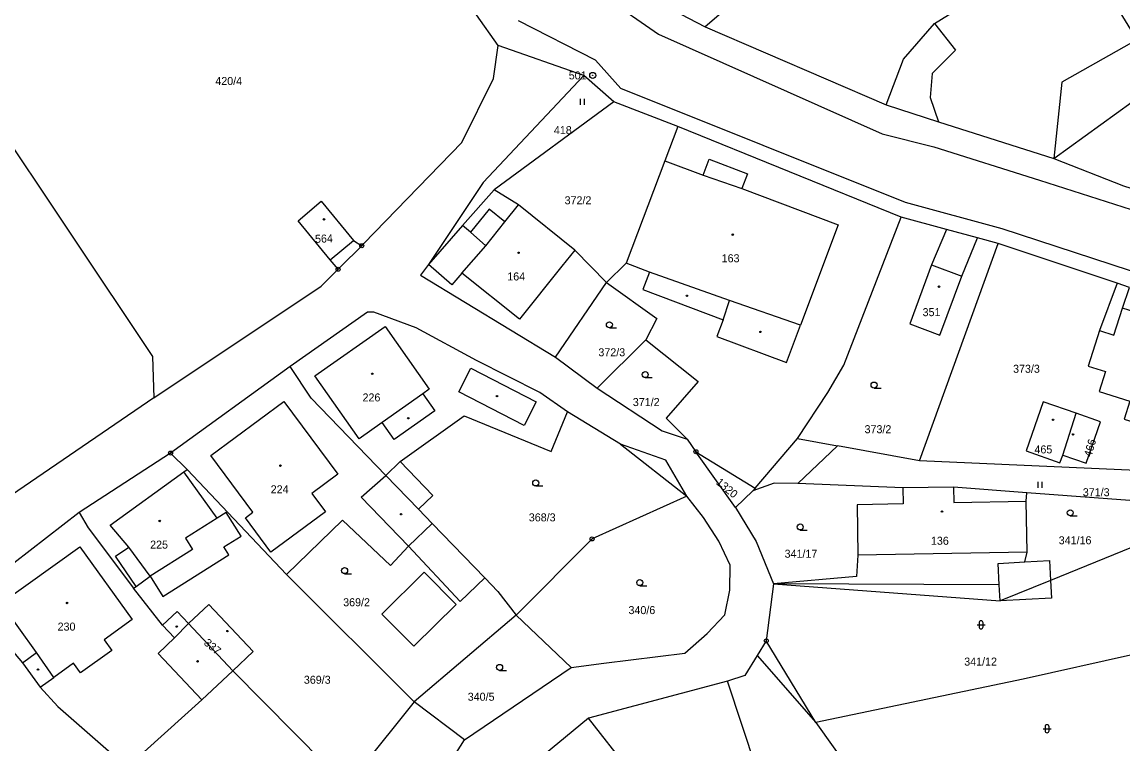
# Model space of a CAD drawing. Extents: x -745926 to -742978, y -968282 to -965689.
# Drawn here: x -744856.3 to -744718.8, y -966688.6 to -966598.4 of the extents above; entities that cross this region are included whole.
import ezdxf

# ---------------------------------------------------------------- set-up
doc = ezdxf.new("R2010")
doc.units = 0
for name, color, linetype in [('Hranice parcel', 7, 'Continuous'), ('Parcelní čísla', 7, 'Continuous'), ('Vnitřní kresba', 7, 'Continuous'), ('Značky bodu BP', 7, 'Continuous'), ('Značky budov', 7, 'Continuous'), ('Značky kultur', 7, 'Continuous')]:
    doc.layers.add(name, color=color, linetype=linetype)

msp = doc.modelspace()

# ---------------------------------------------------------------- linework, layer by layer
at = {"layer": 'Hranice parcel'}
for p, q in [((-744775.05, -966596.92), (-744770.98, -966599.02)), ((-744727.43, -966615.48), (-744701.27, -966596.5)), ((-744786.13, -966605.11), (-744796.84, -966601.38)), ((-744782.39, -966608.41), (-744786.13, -966605.11)), ((-744782.39, -966608.41), (-744797.33, -966619.38)), ((-744774.4, -966611.5), (-744782.39, -966608.41)), ((-744746.47, -966622.79), (-744774.4, -966611.5)), ((-744740.83, -966624.33), (-744746.47, -966622.79)), ((-744736.97, -966625.38), (-744740.83, -966624.33)), ((-744744.18, -966653.24), (-744734.36, -966626.09)), ((-744734.36, -966626.09), (-744736.97, -966625.38)), ((-744719.52, -966631.07), (-744734.36, -966626.09)), ((-744789.67, -966640.3), (-744783.3, -966630.97)), ((-744717.95, -966631.6), (-744719.52, -966631.07)), ((-744778.37, -966638.12), (-744784.48, -966644.17)), ((-744789.67, -966640.3), (-744784.48, -966644.17)), ((-744822.81, -966641.46), (-744837.75, -966652.27)), ((-744781.55, -966651.15), (-744788.18, -966647.11)), ((-744726.31, -966652.51), (-744724.63, -966647.3)), ((-744773.22, -966650.55), (-744772.12, -966652.1)), ((-744764.73, -966656.66), (-744759.45, -966650.45)), ((-744767.18, -966659.06), (-744772.12, -966652.1)), ((-744772.12, -966652.1), (-744764.73, -966656.66)), ((-744754.42, -966651.36), (-744759.4, -966656.05)), ((-744744.18, -966653.24), (-744754.42, -966651.36)), ((-744837.75, -966652.27), (-744849.16, -966659.7)), ((-744837.75, -966652.27), (-744835.66, -966654.34)), ((-744835.66, -966654.34), (-744823.26, -966667.43)), ((-744746.27, -966656.63), (-744759.4, -966656.05)), ((-744765.01, -966656.99), (-744767.18, -966659.06)), ((-744764.73, -966656.66), (-744765.01, -966656.99)), ((-744705.54, -966659.11), (-744730.81, -966657.23)), ((-744849.16, -966659.7), (-744863.06, -966670.44)), ((-744823.26, -966667.43), (-744807.32, -966683.35)), ((-744762.42, -966668.6), (-744734.12, -966670.73)), ((-744794.58, -966672.53), (-744807.32, -966683.35)), ((-744787.69, -966679.04), (-744794.58, -966672.53)), ((-744829.99, -966679.45), (-744835.5, -966673.56)), ((-744764.47, -966677.55), (-744757.14, -966685.91)), ((-744818.49, -966691.06), (-744829.99, -966679.45)), ((-744801.02, -966688.1), (-744787.69, -966679.04)), ((-744768.17, -966680.74), (-744785.56, -966685.37)), ((-744760.83, -966702.86), (-744768.17, -966680.74)), ((-744807.32, -966683.35), (-744815.86, -966693.95)), ((-744801.02, -966688.1), (-744807.32, -966683.35)), ((-744771, -966703.8), (-744785.56, -966685.37)), ((-744757.14, -966685.91), (-744750.62, -966695.06))]:
    msp.add_line(p, q, dxfattribs=at)
for points in [[(-744716.25, -966555.44), (-744752.01, -966582.79), (-744770.98, -966599.02)], [(-744796.84, -966601.38), (-744799.55, -966597.52), (-744839.2, -966562.28)], [(-744701.27, -966596.5), (-744707.68, -966587.65), (-744713.09, -966580.18), (-744722.16, -966586.05), (-744728.83, -966590.26), (-744727, -966593.31), (-744722.74, -966590.77), (-744721.41, -966593.48), (-744717.03, -966600.68), (-744726.42, -966605.96), (-744727.43, -966615.48)], [(-744870.73, -966594.19), (-744840.02, -966640.22), (-744839.84, -966645.38)], [(-744770.98, -966599.02), (-744748.37, -966608.77), (-744741.81, -966610.89), (-744727.43, -966615.48)], [(-744813.87, -966626.37), (-744813.61, -966626.1), (-744801.38, -966613.48), (-744797.42, -966605.5), (-744796.84, -966601.38)], [(-744786.13, -966605.11), (-744798.69, -966618.49), (-744805.52, -966628.71)], [(-744774.4, -966611.5), (-744776, -966615.76), (-744780.83, -966628.57), (-744783.3, -966630.97)], [(-744727.43, -966615.48), (-744718.72, -966618.88), (-744689.3, -966628.22)], [(-744797.33, -966619.38), (-744801.27, -966623.86), (-744805.52, -966628.71)], [(-744783.3, -966630.97), (-744787.25, -966626.91), (-744794.29, -966621.26), (-744797.33, -966619.38)], [(-744816.82, -966629.32), (-744817.8, -966628.13), (-744821.83, -966623.26), (-744818.94, -966620.81), (-744814.91, -966625.73), (-744813.87, -966626.37)], [(-744759.45, -966650.45), (-744755.66, -966644.71), (-744753.65, -966641.28), (-744746.47, -966622.79)], [(-744740.83, -966624.33), (-744742.68, -966628.78), (-744745.4, -966636.14), (-744741.65, -966637.53), (-744738.93, -966630.17), (-744736.97, -966625.38)], [(-744813.87, -966626.37), (-744816.51, -966629.01), (-744816.82, -966629.32)], [(-744805.52, -966628.71), (-744806.51, -966630.06), (-744789.67, -966640.3)], [(-744839.84, -966645.38), (-744818.92, -966631.44), (-744816.82, -966629.32)], [(-744783.3, -966630.97), (-744776.99, -966635.48), (-744778.37, -966638.12)], [(-744719.52, -966631.07), (-744721.73, -966636.96), (-744723.13, -966641.4), (-744720.95, -966642.09), (-744721.74, -966644.57), (-744717.94, -966645.77), (-744718.65, -966648.02), (-744714.36, -966649.37), (-744712.91, -966644.78), (-744711.85, -966645.12), (-744709.34, -966637.16), (-744718.84, -966634.16), (-744717.95, -966631.6)], [(-744788.18, -966647.11), (-744791.61, -966644.69), (-744799.55, -966640.69), (-744807.06, -966636.62), (-744812.37, -966634.67), (-744813.17, -966634.67), (-744822.81, -966641.46)], [(-744778.37, -966638.12), (-744771.83, -966643.35), (-744775.85, -966647.89), (-744773.22, -966650.55)], [(-744810.85, -966655.06), (-744820.19, -966645.4), (-744822.81, -966641.46)], [(-744784.48, -966644.17), (-744776.34, -966649.49), (-744773.22, -966650.55)], [(-744839.84, -966645.38), (-744895.06, -966683.09), (-744895.3, -966683.21)], [(-744724.63, -966647.3), (-744728.74, -966645.86), (-744730.89, -966652), (-744726.65, -966653.49), (-744726.31, -966652.51)], [(-744810.85, -966655.06), (-744809.07, -966653.34), (-744801.07, -966647.61), (-744790.2, -966652.06), (-744788.18, -966647.11)], [(-744726.31, -966652.51), (-744723.39, -966653.53), (-744721.58, -966648.37), (-744724.63, -966647.3)], [(-744773.26, -966657.67), (-744775.88, -966653.17), (-744781.55, -966651.15)], [(-744712.48, -966654.2), (-744715.21, -966654.51), (-744744.18, -966653.24)], [(-744842.36, -966669.15), (-744842.05, -966668.94), (-744840.31, -966667.65), (-744838.72, -966670.17), (-744830.46, -966664.97), (-744831.08, -966663.99), (-744828.95, -966662.65), (-744830.81, -966659.7), (-744831.94, -966660.41), (-744836.1, -966654.63), (-744835.66, -966654.34)], [(-744805.07, -966661.05), (-744806.79, -966659.27), (-744810.85, -966655.06)], [(-744759.4, -966656.05), (-744762.36, -966656.04), (-744765.01, -966656.99)], [(-744773.26, -966657.67), (-744785.1, -966663), (-744794.58, -966672.53)], [(-744787.69, -966679.04), (-744783.61, -966678.5), (-744773.51, -966677.27), (-744770.7, -966674.8), (-744768.5, -966672.49), (-744767.87, -966669.38), (-744767.86, -966666.26), (-744769.28, -966663.29), (-744771.19, -966660.32), (-744773.26, -966657.67)], [(-744746.27, -966656.63), (-744746.23, -966658.62), (-744752, -966658.72), (-744751.89, -966665), (-744752.05, -966667.67), (-744762.42, -966668.6)], [(-744730.81, -966657.23), (-744739.95, -966656.52), (-744746.27, -966656.63)], [(-744734.12, -966670.73), (-744734.23, -966668.74), (-744734.39, -966666.06), (-744731.03, -966665.87), (-744730.75, -966664.64), (-744730.86, -966658.29), (-744730.81, -966657.23)], [(-744767.18, -966659.06), (-744764.6, -966663.33), (-744762.42, -966668.6)], [(-744849.16, -966659.7), (-744848.05, -966661.59), (-744842.36, -966669.15)], [(-744705.54, -966659.11), (-744727.83, -966668.17), (-744734.12, -966670.73)], [(-744823.26, -966667.43), (-744816.26, -966660.66), (-744810.28, -966666.29), (-744808.03, -966663.9), (-744805.07, -966661.05)], [(-744805.07, -966661.05), (-744798.5, -966667.85), (-744796.85, -966669.56), (-744794.58, -966672.53)], [(-744762.42, -966668.6), (-744763.34, -966675.72), (-744764.47, -966677.55)], [(-744835.5, -966673.56), (-744836.93, -966672.05), (-744838.76, -966673.78), (-744842.36, -966669.15)], [(-744863.06, -966670.44), (-744856.26, -966678.45), (-744854.05, -966681.52), (-744851.84, -966683.93), (-744843.15, -966691.5), (-744833.83, -966683.07), (-744829.99, -966679.45)], [(-744829.99, -966679.45), (-744827.44, -966677.04), (-744832.98, -966671.18), (-744835.5, -966673.56)], [(-744703.69, -966674.33), (-744731.26, -966680.52), (-744757.14, -966685.91)], [(-744764.47, -966677.55), (-744766, -966680.03), (-744768.17, -966680.74)], [(-744785.56, -966685.37), (-744792.95, -966691.5), (-744798.91, -966697.31)], [(-744811.42, -966703.17), (-744809.08, -966700.77), (-744801.02, -966688.1)]]:
    msp.add_lwpolyline(points, dxfattribs=at)
at = {"layer": 'Vnitřní kresba'}
for p, q in [((-744742.31, -966598.6), (-744728.83, -966590.26)), ((-744784.32, -966594.72), (-744776.82, -966599.95)), ((-744784.68, -966603.2), (-744794.27, -966598.27)), ((-744776.82, -966599.95), (-744748.86, -966612.41)), ((-744746.18, -966603.06), (-744742.31, -966598.6)), ((-744742.31, -966598.6), (-744739.69, -966601.97)), ((-744739.69, -966601.97), (-744742.63, -966604.88)), ((-744781.5, -966606.73), (-744784.68, -966603.2)), ((-744748.37, -966608.77), (-744746.18, -966603.06)), ((-744742.63, -966604.88), (-744742.88, -966607.88)), ((-744745.94, -966620.99), (-744781.5, -966606.73)), ((-744742.88, -966607.88), (-744741.81, -966610.89)), ((-744748.86, -966612.41), (-744742.39, -966614.04)), ((-744742.39, -966614.04), (-744729.2, -966618.19)), ((-744776, -966615.76), (-744771.22, -966617.55)), ((-744771.22, -966617.55), (-744770.48, -966615.58)), ((-744770.48, -966615.58), (-744765.69, -966617.38)), ((-744771.22, -966617.55), (-744766.4, -966619.24)), ((-744765.69, -966617.38), (-744766.4, -966619.24)), ((-744729.2, -966618.19), (-744690.35, -966630.62)), ((-744766.4, -966619.24), (-744754.35, -966623.78)), ((-744797.97, -966621.81), (-744800.3, -966624.7)), ((-744796, -966623.39), (-744797.97, -966621.81)), ((-744796, -966623.39), (-744794.29, -966621.26)), ((-744733.87, -966624.25), (-744745.94, -966620.99)), ((-744800.3, -966624.7), (-744801.27, -966623.86)), ((-744800.3, -966624.7), (-744798.37, -966626.4)), ((-744798.37, -966626.4), (-744796, -966623.39)), ((-744754.35, -966623.78), (-744759.06, -966636.29)), ((-744704.46, -966633.91), (-744733.87, -966624.25)), ((-744817.8, -966628.13), (-744814.91, -966625.73)), ((-744801.35, -966629.8), (-744798.37, -966626.4)), ((-744787.25, -966626.91), (-744788.86, -966628.92)), ((-744802.62, -966631.25), (-744805.52, -966628.71)), ((-744777.94, -966629.66), (-744780.83, -966628.57)), ((-744742.68, -966628.78), (-744738.93, -966630.17)), ((-744801.35, -966629.8), (-744802.62, -966631.25)), ((-744794.18, -966635.55), (-744801.35, -966629.8)), ((-744788.86, -966628.92), (-744794.18, -966635.55)), ((-744777.94, -966629.66), (-744778.77, -966631.86)), ((-744767.94, -966633.2), (-744777.94, -966629.66)), ((-744778.77, -966631.86), (-744768.72, -966635.64)), ((-744768.72, -966635.64), (-744767.94, -966633.2)), ((-744759.06, -966636.29), (-744767.94, -966633.2)), ((-744719.91, -966637.53), (-744718.84, -966634.16)), ((-744768.72, -966635.64), (-744769.5, -966637.71)), ((-744819.72, -966642.64), (-744810.95, -966636.46)), ((-744810.95, -966636.46), (-744805.43, -966644.29)), ((-744760.82, -966640.97), (-744759.06, -966636.29)), ((-744721.73, -966636.96), (-744719.91, -966637.53)), ((-744769.5, -966637.71), (-744760.82, -966640.97)), ((-744801.75, -966644.61), (-744800.23, -966641.67)), ((-744800.23, -966641.67), (-744792.07, -966645.89)), ((-744814.19, -966650.49), (-744819.72, -966642.64)), ((-744806.23, -966644.85), (-744811.31, -966648.47)), ((-744805.43, -966644.29), (-744806.23, -966644.85)), ((-744806.23, -966644.85), (-744804.73, -966646.98)), ((-744793.6, -966648.83), (-744801.75, -966644.61)), ((-744832.73, -966652.57), (-744823.62, -966645.81)), ((-744823.62, -966645.81), (-744816.86, -966654.91)), ((-744792.07, -966645.89), (-744793.6, -966648.83)), ((-744804.73, -966646.98), (-744809.83, -966650.58)), ((-744811.31, -966648.47), (-744814.19, -966650.49)), ((-744809.83, -966650.58), (-744811.31, -966648.47)), ((-744759.45, -966650.45), (-744754.42, -966651.36)), ((-744781.55, -966651.15), (-744773.26, -966657.67)), ((-744827.48, -966659.66), (-744832.73, -966652.57)), ((-744805, -966657.55), (-744809.07, -966653.34)), ((-744845.29, -966661.26), (-744836.1, -966654.63)), ((-744816.86, -966654.91), (-744820.09, -966657.3)), ((-744813.93, -966657.79), (-744810.85, -966655.06)), ((-744820.09, -966657.3), (-744818.39, -966659.59)), ((-744806.79, -966659.27), (-744805, -966657.55)), ((-744739.95, -966656.52), (-744739.91, -966658.45)), ((-744808.03, -966663.9), (-744813.93, -966657.79)), ((-744739.91, -966658.45), (-744730.86, -966658.29)), ((-744831.94, -966660.41), (-744835.89, -966662.9)), ((-744828.4, -966660.34), (-744827.48, -966659.66)), ((-744825.21, -966664.65), (-744828.4, -966660.34)), ((-744818.39, -966659.59), (-744825.21, -966664.65)), ((-744842.96, -966664.01), (-744845.29, -966661.26)), ((-744835.89, -966662.9), (-744834.99, -966664.31)), ((-744858.92, -966671.03), (-744849.09, -966663.96)), ((-744849.09, -966663.96), (-744842.55, -966673.05)), ((-744844.62, -966665.13), (-744842.96, -966664.01)), ((-744840.31, -966667.65), (-744842.96, -966664.01)), ((-744834.99, -966664.31), (-744840.31, -966667.65)), ((-744801.58, -966670.81), (-744808.03, -966663.9)), ((-744842.05, -966668.94), (-744844.62, -966665.13)), ((-744730.75, -966664.64), (-744751.89, -966665)), ((-744731.03, -966665.87), (-744727.97, -966665.69)), ((-744727.97, -966665.69), (-744727.83, -966668.17)), ((-744811.35, -966672.37), (-744806.07, -966667.15)), ((-744806.07, -966667.15), (-744802.09, -966671.17)), ((-744798.5, -966667.85), (-744801.58, -966670.81)), ((-744734.23, -966668.74), (-744762.42, -966668.6)), ((-744727.83, -966668.17), (-744727.7, -966670.37)), ((-744854.5, -966677.18), (-744858.92, -966671.03)), ((-744802.09, -966671.17), (-744807.37, -966676.39)), ((-744727.7, -966670.37), (-744734.12, -966670.73)), ((-744807.37, -966676.39), (-744811.35, -966672.37)), ((-744842.55, -966673.05), (-744846.06, -966675.58)), ((-744837.26, -966675.36), (-744838.76, -966673.78)), ((-744837.26, -966675.36), (-744835.5, -966673.56)), ((-744846.06, -966675.58), (-744845.1, -966676.92)), ((-744839.29, -966677.28), (-744837.26, -966675.36)), ((-744845.1, -966676.92), (-744849.01, -966679.73)), ((-744757.14, -966685.91), (-744763.34, -966675.72)), ((-744856.26, -966678.45), (-744854.5, -966677.18)), ((-744852.33, -966680.28), (-744854.5, -966677.18)), ((-744833.83, -966683.07), (-744839.29, -966677.28)), ((-744849.89, -966678.52), (-744852.33, -966680.28)), ((-744849.01, -966679.73), (-744849.89, -966678.52)), ((-744854.05, -966681.52), (-744852.33, -966680.28))]:
    msp.add_line(p, q, dxfattribs=at)
at = {"layer": 'Značky bodu BP'}
for centre, radius in [((-744785.02, -966605.1), 0.375), ((-744785.02, -966605.1), 0.015), ((-744813.87, -966626.37), 0.25), ((-744813.87, -966626.37), 0.0152), ((-744816.82, -966629.32), 0.25), ((-744816.82, -966629.32), 0.0152), ((-744837.75, -966652.27), 0.25), ((-744772.12, -966652.1), 0.25), ((-744772.12, -966652.1), 0.0152), ((-744837.75, -966652.27), 0.0152), ((-744785.1, -966663), 0.25), ((-744785.1, -966663), 0.0152), ((-744763.34, -966675.72), 0.25), ((-744763.34, -966675.72), 0.0152)]:
    msp.add_circle(centre, radius, dxfattribs=at)
at = {"layer": 'Značky budov'}
for centre in [(-744818.58, -966623.08), (-744767.53, -966624.99), (-744794.28, -966627.26), (-744741.76, -966631.49), (-744773.25, -966632.63), (-744764.06, -966637.14), (-744812.56, -966642.37), (-744796.97, -966645.15), (-744808.06, -966647.92), (-744727.51, -966648.11), (-744725.01, -966649.94), (-744824.03, -966653.84), (-744808.96, -966659.91), (-744741.39, -966659.58), (-744839.11, -966660.75), (-744850.67, -966670.99), (-744836.98, -966673.94), (-744830.64, -966674.51), (-744834.38, -966678.28), (-744854.31, -966679.31)]:
    msp.add_circle(centre, 0.0875, dxfattribs=at)
at = {"layer": 'Značky kultur'}
for p, q in [((-744786.56, -966608.79), (-744786.56, -966608.04)), ((-744786.06, -966608.79), (-744786.06, -966608.04)), ((-744782.94, -966636.63), (-744782.06, -966636.63)), ((-744778.46, -966642.85), (-744777.58, -966642.85)), ((-744749.87, -966644.15), (-744748.99, -966644.15)), ((-744729.37, -966656.61), (-744729.37, -966655.86)), ((-744728.86, -966656.61), (-744728.86, -966655.86)), ((-744792.14, -966656.38), (-744791.26, -966656.38)), ((-744725.37, -966660.11), (-744724.49, -966660.11)), ((-744759.1, -966661.88), (-744758.22, -966661.88)), ((-744816.01, -966667.33), (-744815.13, -966667.33)), ((-744779.14, -966668.83), (-744778.26, -966668.83)), ((-744737.01, -966673.72), (-744736.01, -966673.72)), ((-744736.76, -966673.47), (-744736.76, -966673.97)), ((-744736.26, -966673.97), (-744736.26, -966673.47)), ((-744796.65, -966679.41), (-744795.77, -966679.41)), ((-744728.52, -966686.44), (-744728.52, -966686.94)), ((-744728.02, -966686.94), (-744728.02, -966686.44)), ((-744728.77, -966686.69), (-744727.77, -966686.69))]:
    msp.add_line(p, q, dxfattribs=at)
for centre in [(-744782.94, -966636.25), (-744778.46, -966642.47), (-744749.87, -966643.77), (-744792.14, -966656), (-744725.37, -966659.73), (-744759.1, -966661.5), (-744816.01, -966666.95), (-744779.14, -966668.45), (-744796.65, -966679.03)]:
    msp.add_circle(centre, 0.375, dxfattribs=at)
for centre, start, end in [((-744736.51, -966673.47), 0, 180), ((-744736.51, -966673.97), 180, 359.9879), ((-744728.27, -966686.44), 0, 180), ((-744728.27, -966686.94), 180, 359.9879)]:
    msp.add_arc(centre, 0.25, start, end, dxfattribs=at)

# ---------------------------------------------------------------- texts
at = {"layer": 'Parcelní čísla'}
for s, p in [('420/4', (-744832.16, -966606.3)), ('418', (-744789.87, -966612.44)), ('372/2', (-744788.53, -966621.2)), ('163', (-744768.91, -966628.44)), ('164', (-744795.69, -966630.71)), ('351', (-744743.81, -966635.17)), ('372/3', (-744784.31, -966640.18)), ('373/3', (-744732.51, -966642.24)), ('226', (-744813.77, -966645.82)), ('371/2', (-744780.01, -966646.4)), ('373/2', (-744751.06, -966649.79)), ('465', (-744729.84, -966652.31)), ('224', (-744825.24, -966657.29)), ('371/3', (-744723.8, -966657.66)), ('368/3', (-744793, -966660.8)), ('225', (-744840.3, -966664.2)), ('136', (-744742.77, -966663.72)), ('341/16', (-744726.81, -966663.66)), ('341/17', (-744761.05, -966665.34)), ('369/2', (-744816.19, -966671.4)), ('340/6', (-744780.55, -966672.38)), ('230', (-744851.86, -966674.44)), ('341/12', (-744738.61, -966678.81)), ('369/3', (-744821.1, -966681.08)), ('340/5', (-744800.63, -966683.2))]:
    msp.add_text(s, height=1, dxfattribs=at).set_placement(p)
for s, rotation, p in [('564', 2, (-744819.69, -966626.02)), ('466', 74, (-744722.73, -966652.83)), ('1320', 320, (-744769.71, -966656.06)), ('337', 320, (-744833.68, -966676.11))]:
    msp.add_text(s, height=1, rotation=rotation, dxfattribs=at).set_placement(p)
at = {"layer": 'Značky bodu BP'}
msp.add_text('501', height=1, dxfattribs=at).set_placement((-744788.01, -966605.6))

doc.saveas('drawing.dxf')
